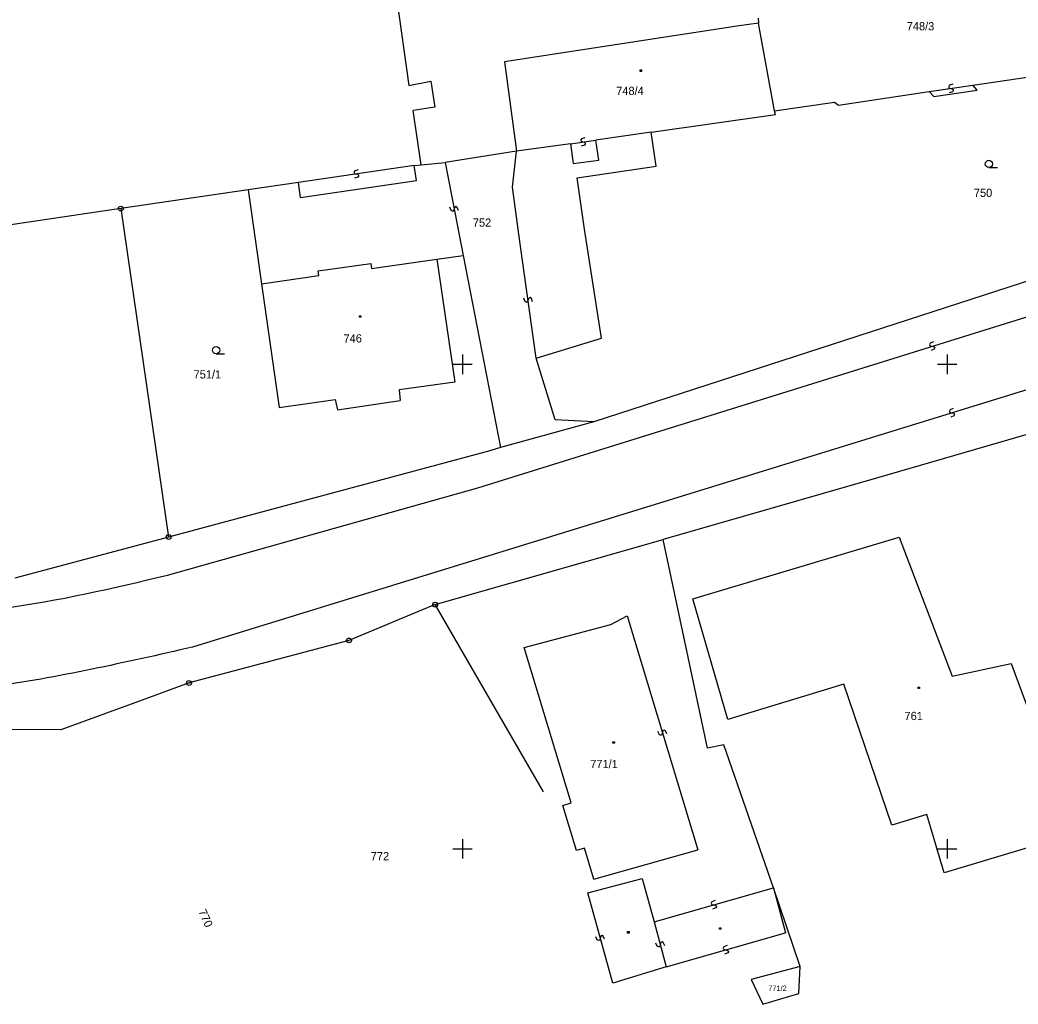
# Model space of a CAD drawing. Extents: x -493648 to -493033, y -1127718 to -1127026.
# Drawn here: x -493495.7 to -493392.7, y -1127716 to -1127614.5 of the extents above; entities that cross this region are included whole.
import ezdxf

# ---------------------------------------------------------------- set-up
doc = ezdxf.new("R2010")
doc.units = 0
doc.layers.add('katastrální mapa', color=7, linetype='Continuous')
doc.layers.add('síť', color=7, linetype='Continuous')

msp = doc.modelspace()

# ---------------------------------------------------------------- linework, layer by layer
at = {"layer": 'katastrální mapa'}
for p, q in [((-493457.12, -1127609.97), (-493455.52, -1127621.22)), ((-493419.45, -1127614.81), (-493421.46, -1127615.07)), ((-493419.51, -1127614.29), (-493419.45, -1127614.81)), ((-493417.81, -1127623.84), (-493419.45, -1127614.81)), ((-493421.46, -1127615.07), (-493445.65, -1127618.78)), ((-493445.65, -1127618.78), (-493444.41, -1127628.01)), ((-493431.68, -1127619.62), (-493431.53, -1127619.62)), ((-493431.68, -1127619.77), (-493431.68, -1127619.62)), ((-493431.53, -1127619.77), (-493431.68, -1127619.77)), ((-493431.53, -1127619.62), (-493431.53, -1127619.77)), ((-493397.36, -1127621.21), (-493387.25, -1127619.72)), ((-493455.52, -1127621.22), (-493453.26, -1127620.8)), ((-493453.26, -1127620.8), (-493452.85, -1127623.48)), ((-493399.41, -1127621.1), (-493399.75, -1127621.2)), ((-493411.22, -1127623.25), (-493401.85, -1127621.86)), ((-493401.85, -1127621.86), (-493397.36, -1127621.21)), ((-493401.85, -1127621.86), (-493401.38, -1127622.37)), ((-493401.38, -1127622.37), (-493396.91, -1127621.72)), ((-493399.75, -1127621.2), (-493399.84, -1127621.32)), ((-493399.84, -1127621.32), (-493399.82, -1127621.42)), ((-493399.82, -1127621.42), (-493399.71, -1127621.5)), ((-493399.46, -1127621.87), (-493399.8, -1127621.97)), ((-493399.71, -1127621.5), (-493399.5, -1127621.57)), ((-493399.5, -1127621.57), (-493399.39, -1127621.65)), ((-493399.37, -1127621.75), (-493399.46, -1127621.87)), ((-493399.39, -1127621.65), (-493399.37, -1127621.75)), ((-493396.91, -1127621.72), (-493397.36, -1127621.21)), ((-493417.81, -1127623.84), (-493411.61, -1127622.96)), ((-493411.61, -1127622.96), (-493411.22, -1127623.25)), ((-493452.85, -1127623.48), (-493455.1, -1127623.8)), ((-493454.26, -1127629.42), (-493455.1, -1127623.8)), ((-493430.54, -1127626.03), (-493417.69, -1127624.22)), ((-493417.69, -1127624.22), (-493417.81, -1127623.84)), ((-493341.88, -1127625.25), (-493393.65, -1127642.03)), ((-493430.54, -1127626.03), (-493436.25, -1127626.86)), ((-493430.03, -1127629.57), (-493430.54, -1127626.03)), ((-493438.87, -1127627.24), (-493444.41, -1127628.01)), ((-493438.87, -1127627.24), (-493436.25, -1127626.86)), ((-493438.87, -1127627.24), (-493438.58, -1127629.28)), ((-493437.71, -1127626.72), (-493437.79, -1127626.83)), ((-493437.79, -1127626.83), (-493437.78, -1127626.93)), ((-493437.78, -1127626.93), (-493437.67, -1127627.01)), ((-493437.37, -1127626.62), (-493437.71, -1127626.72)), ((-493437.67, -1127627.01), (-493437.45, -1127627.09)), ((-493437.45, -1127627.09), (-493437.34, -1127627.17)), ((-493437.33, -1127627.27), (-493437.41, -1127627.38)), ((-493437.34, -1127627.17), (-493437.33, -1127627.27)), ((-493435.94, -1127628.95), (-493436.25, -1127626.86)), ((-493444.41, -1127628.01), (-493451.79, -1127629.17)), ((-493444.84, -1127631.72), (-493444.41, -1127628.01)), ((-493437.41, -1127627.38), (-493437.75, -1127627.48)), ((-493454.97, -1127629.48), (-493454.26, -1127629.42)), ((-493454.26, -1127629.42), (-493451.79, -1127629.17)), ((-493451.79, -1127629.17), (-493449.93, -1127638.77)), ((-493438.58, -1127629.28), (-493435.94, -1127628.95)), ((-493454.97, -1127629.48), (-493466.93, -1127631.24)), ((-493461.1, -1127630.03), (-493461.18, -1127630.14)), ((-493461.18, -1127630.14), (-493461.17, -1127630.24)), ((-493461.17, -1127630.24), (-493461.06, -1127630.33)), ((-493460.76, -1127629.93), (-493461.1, -1127630.03)), ((-493461.06, -1127630.33), (-493460.84, -1127630.39)), ((-493460.84, -1127630.39), (-493460.73, -1127630.48)), ((-493454.75, -1127631.02), (-493454.97, -1127629.48)), ((-493438.15, -1127630.75), (-493430.03, -1127629.57)), ((-493395.69, -1127629.7), (-493394.81, -1127629.7)), ((-493466.93, -1127631.24), (-493472.1, -1127632)), ((-493466.7, -1127632.8), (-493466.93, -1127631.24)), ((-493466.7, -1127632.8), (-493454.75, -1127631.02)), ((-493460.8, -1127630.69), (-493461.14, -1127630.79)), ((-493460.72, -1127630.58), (-493460.8, -1127630.69)), ((-493460.73, -1127630.48), (-493460.72, -1127630.58)), ((-493437.41, -1127636.07), (-493438.15, -1127630.75)), ((-493472.1, -1127632), (-493485.24, -1127633.93)), ((-493472.1, -1127632), (-493470.73, -1127641.69)), ((-493444.07, -1127637.34), (-493444.84, -1127631.72)), ((-493448.42, -1127662.75), (-493354.66, -1127633.52)), ((-493485.24, -1127633.93), (-493500.78, -1127636.21)), ((-493485.24, -1127633.93), (-493480.31, -1127667.82)), ((-493451.18, -1127634.13), (-493451.3, -1127633.8)), ((-493451.07, -1127634.21), (-493451.18, -1127634.13)), ((-493450.97, -1127634.19), (-493451.07, -1127634.21)), ((-493450.89, -1127634.08), (-493450.97, -1127634.19)), ((-493450.83, -1127633.86), (-493450.89, -1127634.08)), ((-493450.75, -1127633.75), (-493450.83, -1127633.86)), ((-493450.65, -1127633.73), (-493450.75, -1127633.75)), ((-493450.54, -1127633.81), (-493450.65, -1127633.73)), ((-493450.42, -1127634.14), (-493450.54, -1127633.81)), ((-493435.64, -1127647.29), (-493437.41, -1127636.07)), ((-493442.38, -1127649.36), (-493444.07, -1127637.34)), ((-493464.88, -1127640.35), (-493459.44, -1127639.61)), ((-493459.44, -1127639.61), (-493459.37, -1127640.1)), ((-493459.37, -1127640.1), (-493452.64, -1127639.16)), ((-493452.64, -1127639.16), (-493449.93, -1127638.77)), ((-493452.64, -1127639.16), (-493450.79, -1127651.85)), ((-493449.93, -1127638.77), (-493446.09, -1127658.58)), ((-493464.81, -1127640.84), (-493464.88, -1127640.35)), ((-493352.18, -1127640.4), (-493446.83, -1127669.61)), ((-493470.73, -1127641.69), (-493464.81, -1127640.84)), ((-493470.73, -1127641.69), (-493468.92, -1127654.45)), ((-493393.65, -1127642.03), (-493436.46, -1127655.95)), ((-493443.56, -1127643.5), (-493443.66, -1127643.16)), ((-493443.44, -1127643.58), (-493443.56, -1127643.5)), ((-493443.35, -1127643.57), (-493443.44, -1127643.58)), ((-493443.26, -1127643.46), (-493443.35, -1127643.57)), ((-493443.19, -1127643.24), (-493443.26, -1127643.46)), ((-493443.1, -1127643.13), (-493443.19, -1127643.24)), ((-493443.01, -1127643.12), (-493443.1, -1127643.13)), ((-493442.89, -1127643.2), (-493443.01, -1127643.12)), ((-493442.79, -1127643.54), (-493442.89, -1127643.2)), ((-493460.63, -1127644.99), (-493460.48, -1127644.99)), ((-493460.63, -1127645.14), (-493460.63, -1127644.99)), ((-493460.48, -1127645.14), (-493460.63, -1127645.14)), ((-493460.48, -1127644.99), (-493460.48, -1127645.14)), ((-493442.38, -1127649.36), (-493435.64, -1127647.29)), ((-493401.74, -1127647.83), (-493401.81, -1127647.96)), ((-493401.81, -1127647.96), (-493401.78, -1127648.05)), ((-493401.42, -1127647.68), (-493401.74, -1127647.83)), ((-493475.42, -1127648.91), (-493474.54, -1127648.91)), ((-493401.78, -1127648.05), (-493401.65, -1127648.12)), ((-493401.34, -1127648.44), (-493401.66, -1127648.59)), ((-493401.65, -1127648.12), (-493401.43, -1127648.15)), ((-493401.43, -1127648.15), (-493401.3, -1127648.22)), ((-493401.27, -1127648.31), (-493401.34, -1127648.44)), ((-493401.3, -1127648.22), (-493401.27, -1127648.31)), ((-493440.43, -1127655.73), (-493442.38, -1127649.36)), ((-493365.84, -1127649.73), (-493407.29, -1127661.76)), ((-493450.79, -1127651.85), (-493456.52, -1127652.65)), ((-493456.52, -1127652.65), (-493456.42, -1127653.72)), ((-493468.92, -1127654.45), (-493463.13, -1127653.63)), ((-493463.13, -1127653.63), (-493462.9, -1127654.68)), ((-493462.9, -1127654.68), (-493456.42, -1127653.72)), ((-493399.7, -1127654.7), (-493399.77, -1127654.83)), ((-493399.77, -1127654.83), (-493399.74, -1127654.92)), ((-493399.74, -1127654.92), (-493399.62, -1127654.99)), ((-493399.38, -1127654.55), (-493399.7, -1127654.7)), ((-493399.62, -1127654.99), (-493399.39, -1127655.02)), ((-493399.39, -1127655.02), (-493399.27, -1127655.09)), ((-493399.27, -1127655.09), (-493399.24, -1127655.18)), ((-493436.46, -1127655.95), (-493446.09, -1127658.58)), ((-493436.46, -1127655.95), (-493440.43, -1127655.73)), ((-493399.31, -1127655.31), (-493399.63, -1127655.46)), ((-493399.24, -1127655.18), (-493399.31, -1127655.31)), ((-493447.17, -1127658.92), (-493480.31, -1127667.82)), ((-493446.09, -1127658.58), (-493447.17, -1127658.92)), ((-493407.29, -1127661.76), (-493429.28, -1127668.06)), ((-493480.43, -1127671.75), (-493448.42, -1127662.75)), ((-493480.31, -1127667.82), (-493496.17, -1127672.08)), ((-493452.81, -1127674.8), (-493429.28, -1127668.06)), ((-493424.73, -1127689.61), (-493429.28, -1127668.06)), ((-493426.25, -1127674.21), (-493404.96, -1127667.84)), ((-493404.96, -1127667.84), (-493399.48, -1127682.18)), ((-493446.83, -1127669.61), (-493477.84, -1127679.18)), ((-493422.63, -1127686.66), (-493426.25, -1127674.21)), ((-493452.81, -1127674.8), (-493461.71, -1127678.49)), ((-493441.65, -1127694.1), (-493452.81, -1127674.8)), ((-493434.68, -1127676.86), (-493433.02, -1127675.94)), ((-493433.02, -1127675.94), (-493425.73, -1127700.1)), ((-493443.62, -1127679.21), (-493434.68, -1127676.86)), ((-493461.71, -1127678.49), (-493478.21, -1127682.88)), ((-493438.78, -1127695.25), (-493443.62, -1127679.21)), ((-493399.48, -1127682.18), (-493393.38, -1127680.88)), ((-493393.38, -1127680.88), (-493389.1, -1127692.54)), ((-493478.21, -1127682.88), (-493483.06, -1127684.65)), ((-493410.66, -1127682.99), (-493422.63, -1127686.66)), ((-493405.7, -1127697.54), (-493410.66, -1127682.99)), ((-493403, -1127683.3), (-493402.85, -1127683.3)), ((-493403, -1127683.45), (-493403, -1127683.3)), ((-493402.85, -1127683.45), (-493403, -1127683.45)), ((-493402.85, -1127683.3), (-493402.85, -1127683.45)), ((-493483.06, -1127684.65), (-493486.72, -1127685.99)), ((-493486.72, -1127685.99), (-493491.42, -1127687.7)), ((-493491.42, -1127687.7), (-493514.66, -1127687.58)), ((-493429.68, -1127688.22), (-493429.83, -1127687.9)), ((-493429.36, -1127687.91), (-493429.39, -1127688.13)), ((-493429.29, -1127687.79), (-493429.36, -1127687.91)), ((-493429.19, -1127687.76), (-493429.29, -1127687.79)), ((-493429.07, -1127687.82), (-493429.19, -1127687.76)), ((-493428.92, -1127688.14), (-493429.07, -1127687.82)), ((-493434.48, -1127688.95), (-493434.33, -1127688.95)), ((-493434.48, -1127689.1), (-493434.48, -1127688.95)), ((-493434.33, -1127689.1), (-493434.48, -1127689.1)), ((-493434.33, -1127688.95), (-493434.33, -1127689.1)), ((-493429.56, -1127688.28), (-493429.68, -1127688.22)), ((-493429.46, -1127688.25), (-493429.56, -1127688.28)), ((-493429.39, -1127688.13), (-493429.46, -1127688.25)), ((-493423.02, -1127689.25), (-493424.73, -1127689.61)), ((-493417.91, -1127704.02), (-493423.02, -1127689.25)), ((-493439.63, -1127695.51), (-493438.78, -1127695.25)), ((-493438.23, -1127700.18), (-493439.63, -1127695.51)), ((-493402.1, -1127696.46), (-493405.7, -1127697.54)), ((-493400.29, -1127702.48), (-493402.1, -1127696.46)), ((-493388.23, -1127698.85), (-493400.29, -1127702.48)), ((-493437.4, -1127699.93), (-493438.23, -1127700.18)), ((-493436.44, -1127703.13), (-493437.4, -1127699.93)), ((-493436.44, -1127703.13), (-493425.73, -1127700.1)), ((-493437.08, -1127704.55), (-493431.47, -1127703.05)), ((-493431.47, -1127703.05), (-493430.22, -1127707.54)), ((-493434.48, -1127713.84), (-493437.08, -1127704.55)), ((-493430.22, -1127707.54), (-493417.91, -1127704.02)), ((-493417.91, -1127704.02), (-493416.69, -1127708.67)), ((-493415.15, -1127712.15), (-493417.91, -1127704.02)), ((-493424.26, -1127705.47), (-493424.33, -1127705.59)), ((-493424.33, -1127705.59), (-493424.3, -1127705.69)), ((-493423.93, -1127705.33), (-493424.26, -1127705.47)), ((-493424.3, -1127705.69), (-493424.17, -1127705.76)), ((-493423.87, -1127706.09), (-493424.2, -1127706.23)), ((-493424.17, -1127705.76), (-493423.96, -1127705.8)), ((-493423.96, -1127705.8), (-493423.83, -1127705.87)), ((-493423.8, -1127705.97), (-493423.87, -1127706.09)), ((-493423.83, -1127705.87), (-493423.8, -1127705.97)), ((-493430.22, -1127707.54), (-493428.97, -1127712.18)), ((-493432.96, -1127708.53), (-493432.81, -1127708.53)), ((-493432.96, -1127708.68), (-493432.96, -1127708.53)), ((-493432.81, -1127708.68), (-493432.96, -1127708.68)), ((-493432.81, -1127708.53), (-493432.81, -1127708.68)), ((-493428.97, -1127712.18), (-493416.69, -1127708.67)), ((-493423.49, -1127708.13), (-493423.34, -1127708.13)), ((-493423.49, -1127708.28), (-493423.49, -1127708.13)), ((-493423.34, -1127708.28), (-493423.49, -1127708.28)), ((-493423.34, -1127708.13), (-493423.34, -1127708.28)), ((-493436.09, -1127709.39), (-493436.23, -1127709.06)), ((-493435.97, -1127709.45), (-493436.09, -1127709.39)), ((-493435.87, -1127709.43), (-493435.97, -1127709.45)), ((-493435.8, -1127709.3), (-493435.87, -1127709.43)), ((-493435.76, -1127709.09), (-493435.8, -1127709.3)), ((-493435.69, -1127708.96), (-493435.76, -1127709.09)), ((-493435.59, -1127708.94), (-493435.69, -1127708.96)), ((-493435.47, -1127709), (-493435.59, -1127708.94)), ((-493435.33, -1127709.33), (-493435.47, -1127709)), ((-493429.91, -1127710.05), (-493430.05, -1127709.72)), ((-493429.5, -1127709.63), (-493429.57, -1127709.75)), ((-493429.41, -1127709.6), (-493429.5, -1127709.63)), ((-493429.28, -1127709.67), (-493429.41, -1127709.6)), ((-493429.14, -1127710), (-493429.28, -1127709.67)), ((-493429.78, -1127710.12), (-493429.91, -1127710.05)), ((-493429.69, -1127710.09), (-493429.78, -1127710.12)), ((-493429.62, -1127709.97), (-493429.69, -1127710.09)), ((-493429.57, -1127709.75), (-493429.62, -1127709.97)), ((-493423.02, -1127710.12), (-493423.09, -1127710.24)), ((-493423.09, -1127710.24), (-493423.06, -1127710.34)), ((-493423.06, -1127710.34), (-493422.94, -1127710.4)), ((-493422.7, -1127709.97), (-493423.02, -1127710.12)), ((-493422.64, -1127710.73), (-493422.96, -1127710.88)), ((-493422.94, -1127710.4), (-493422.72, -1127710.45)), ((-493422.72, -1127710.45), (-493422.6, -1127710.51)), ((-493422.57, -1127710.61), (-493422.64, -1127710.73)), ((-493422.6, -1127710.51), (-493422.57, -1127710.61)), ((-493428.97, -1127712.18), (-493434.48, -1127713.84)), ((-493415.15, -1127712.15), (-493420.2, -1127713.47)), ((-493415.29, -1127714.93), (-493415.15, -1127712.15)), ((-493420.2, -1127713.47), (-493419.02, -1127716.01)), ((-493419.02, -1127716.01), (-493415.29, -1127714.93))]:
    msp.add_line(p, q, dxfattribs=at)
for centre, radius in [((-493395.69, -1127629.325), 0.375), ((-493485.24, -1127633.93), 0.25), ((-493485.24, -1127633.93), 0.005), ((-493475.42, -1127648.535), 0.375), ((-493480.31, -1127667.82), 0.25), ((-493480.31, -1127667.82), 0.005), ((-493452.81, -1127674.8), 0.25), ((-493452.81, -1127674.8), 0.005), ((-493461.71, -1127678.49), 0.25), ((-493461.71, -1127678.49), 0.005), ((-493478.21, -1127682.88), 0.25), ((-493478.21, -1127682.88), 0.005)]:
    msp.add_circle(centre, radius, dxfattribs=at)
for points in [[(-493547.35, -1127671), (-493529.27, -1127674.47), (-493513.04, -1127675.89), (-493497.42, -1127675.17), (-493480.43, -1127671.75)], [(-493477.84, -1127679.18), (-493498.76, -1127683.3), (-493514.29, -1127684.06), (-493530.78, -1127681.53), (-493547.86, -1127678.6)]]:
    msp.add_spline(points, degree=3, dxfattribs=at)
at = {"layer": 'síť'}
for p, q in [((-493451, -1127650), (-493449, -1127650)), ((-493450, -1127649), (-493450, -1127651)), ((-493401, -1127650), (-493399, -1127650)), ((-493400, -1127649), (-493400, -1127651)), ((-493450, -1127699), (-493450, -1127701)), ((-493400, -1127699), (-493400, -1127701)), ((-493451, -1127700), (-493449, -1127700)), ((-493401, -1127700), (-493399, -1127700))]:
    msp.add_line(p, q, dxfattribs=at)

# ---------------------------------------------------------------- texts
at = {"layer": 'katastrální mapa'}
for s, height, p in [('748/3', 0.849996, (-493404.17, -1127615.54)), ('748/4', 0.849996, (-493434.14, -1127622.21)), ('750', 0.849996, (-493397.24, -1127632.73)), ('752', 0.849996, (-493448.93, -1127635.8)), ('746', 0.849996, (-493462.27, -1127647.75)), ('751/1', 0.849996, (-493477.74, -1127651.46)), ('761', 0.849996, (-493404.4, -1127686.71)), ('771/1', 0.849996, (-493436.82, -1127691.67)), ('772', 0.849996, (-493459.46, -1127701.17)), ('771/2', 0.569994, (-493418.46, -1127714.67))]:
    msp.add_text(s, height=height, dxfattribs=at).set_placement(p)
msp.add_text('770', height=0.849996, rotation=294.3, dxfattribs=at).set_placement((-493477.27, -1127706.46))

doc.saveas('drawing.dxf')
